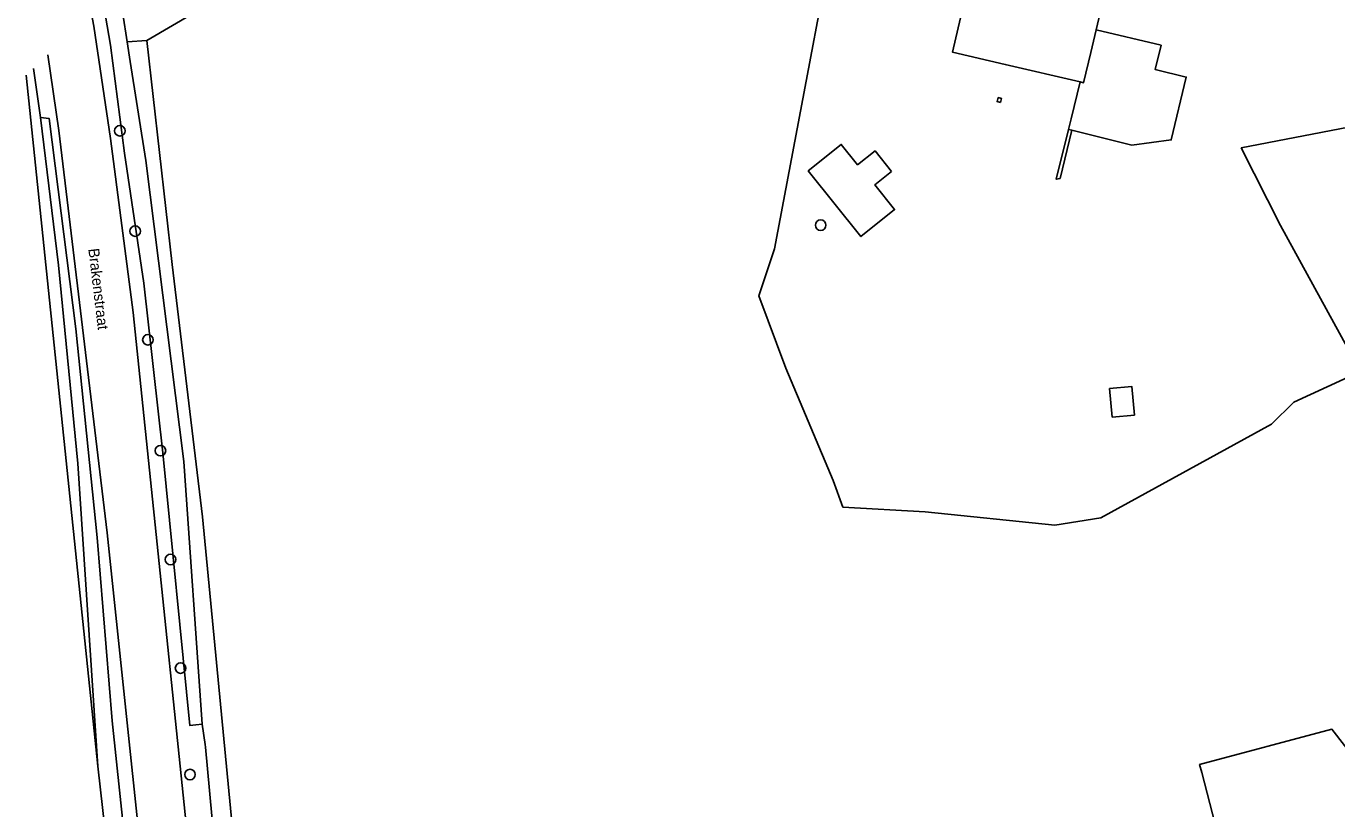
# Model space of a CAD drawing. Extents: x 163863 to 164644, y 379566 to 382155.
# Drawn here: x 164358.4 to 164479.7, y 382019.3 to 382091.7 of the extents above; entities that cross this region are included whole.
import ezdxf

# ---------------------------------------------------------------- set-up
doc = ezdxf.new("R2010")
doc.units = 0
for name, color, linetype in [('IMGEO_Boom', 7, 'Continuous'), ('IMGEO_Grasland_agrarisch', 7, 'Continuous'), ('IMGEO_Grasland_overig', 7, 'Continuous'), ('IMGEO_Hek', 7, 'Continuous'), ('IMGEO_Loofbos', 7, 'Continuous'), ('IMGEO_Muur', 7, 'Continuous'), ('IMGEO_Openbare_ruimte_label', 7, 'Continuous'), ('IMGEO_Pand', 7, 'Continuous'), ('IMGEO_Rijbaan_lokaal_halfverhard', 7, 'Continuous'), ('IMGEO_Waterloop', 7, 'Continuous')]:
    doc.layers.add(name, color=color, linetype=linetype)

msp = doc.modelspace()

# ---------------------------------------------------------------- linework, layer by layer
at = {"layer": 'IMGEO_Boom'}
for centre in [(164367.08, 382082.06), (164368.5, 382072.77), (164431.95, 382073.32), (164369.68, 382062.71), (164370.84, 382052.45), (164371.77, 382042.37), (164372.7, 382032.32), (164373.58, 382022.46)]:
    msp.add_circle(centre, 0.489, dxfattribs=at)
at = {"layer": 'IMGEO_Grasland_agrarisch'}
for points in [[(164489.95, 382084.16), (164470.87, 382080.47), (164474.51, 382073.3), (164481.92, 382059.76), (164475.75, 382056.93), (164473.68, 382054.91), (164457.89, 382046.24), (164453.63, 382045.54), (164441.62, 382046.78), (164434.01, 382047.23), (164433.1, 382049.68), (164428.71, 382060.09), (164426.21, 382066.78), (164427.68, 382071.12), (164435.11, 382110.54)], [(164387.83, 382106.04), (164385.99, 382095.61), (164373.96, 382092.98), (164369.59, 382090.41)]]:
    msp.add_lwpolyline(points, dxfattribs=at)
at = {"layer": 'IMGEO_Grasland_overig'}
for points in [[(164367.77, 382090.28), (164369.59, 382090.41)], [(164369.59, 382090.41), (164371.92, 382069.69), (164374.73, 382046.33), (164377.32, 382019.35), (164380.2, 381990.41), (164381.79, 381978.08)], [(164374.69, 382027.13), (164374.98, 382025.23), (164375, 382024.99), (164377.32, 381999.91), (164378.62, 381987.8), (164379.45, 381980.13), (164379.72, 381978.95)], [(164498.03, 382004.23), (164485.7, 382001.51), (164473.39, 381998.73), (164467.22, 382022.66), (164467.02, 382023.39), (164479.26, 382026.66), (164481.61, 382023.65), (164483.42, 382017.63), (164484.77, 382010.15), (164484.92, 382009.26), (164491.77, 382011.05), (164494.28, 382009.65), (164498.03, 382004.23)]]:
    msp.add_lwpolyline(points, dxfattribs=at)
at = {"layer": 'IMGEO_Hek'}
msp.add_lwpolyline([(164358.42, 382087.21), (164365.06, 382023.24)], dxfattribs=at)
at = {"layer": 'IMGEO_Loofbos'}
for points in [[(164359.08, 382087.82), (164359.75, 382083.3)], [(164365.06, 382023.24), (164358.42, 382087.21)]]:
    msp.add_lwpolyline(points, dxfattribs=at)
at = {"layer": 'IMGEO_Muur'}
msp.add_lwpolyline([(164455.21, 382082.11), (164454.11, 382077.65), (164453.76, 382077.58), (164454.89, 382082.19)], dxfattribs=at)
at = {"layer": 'IMGEO_Pand'}
for points in [[(164455.96, 382086.58), (164449.04, 382088.21), (164444.15, 382089.35), (164445.11, 382093.44), (164445.13, 382093.51), (164441.98, 382094.25), (164443.53, 382100.82), (164443.27, 382100.89), (164441.68, 382101.29), (164442.38, 382104.17)], [(164460.32, 382103.62), (164457.45, 382091.42)], [(164457.45, 382091.42), (164463.45, 382089.97), (164462.91, 382087.72), (164465.79, 382087.03), (164464.39, 382081.22), (164460.74, 382080.74), (164455.21, 382082.11)], [(164457.45, 382091.42), (164456.96, 382089.32), (164456.29, 382086.5), (164455.96, 382086.58)], [(164454.89, 382082.19), (164455.13, 382083.17), (164455.96, 382086.58)], [(164448.58, 382084.68), (164448.28, 382084.76), (164448.38, 382085.13), (164448.68, 382085.05), (164448.58, 382084.68)], [(164454.89, 382082.19), (164455.21, 382082.11)], [(164438.51, 382078.3), (164436.95, 382077.05), (164438.79, 382074.76), (164435.68, 382072.26), (164430.8, 382078.35), (164433.85, 382080.8), (164435.36, 382078.91), (164436.98, 382080.2), (164438.51, 382078.3)], [(164461.01, 382055.74), (164458.93, 382055.55), (164458.69, 382058.19), (164460.76, 382058.38), (164461.01, 382055.74)]]:
    msp.add_lwpolyline(points, dxfattribs=at)
at = {"layer": 'IMGEO_Rijbaan_lokaal_halfverhard'}
for points in [[(164394.68, 381881.88), (164388.1, 381917.44), (164387.74, 381919.59), (164379.47, 381969.66), (164377.03, 381983.08), (164376.33, 381987.84), (164375.07, 382000), (164368.33, 382065.24), (164366.23, 382081.36), (164364.66, 382091.74), (164362.19, 382105.09)], [(164360.43, 382089.08), (164361.43, 382082.09), (164365.91, 382044.84), (164370.62, 382000), (164372.7, 381981.96), (164377.52, 381953.78), (164381.31, 381930.61), (164383.71, 381918.93), (164384.14, 381916.84), (164390.52, 381880.76)]]:
    msp.add_lwpolyline(points, dxfattribs=at)
at = {"layer": 'IMGEO_Waterloop'}
for points in [[(164365.2, 382106.99), (164365.73, 382102.34), (164366.27, 382099.76), (164367.36, 382092.89), (164367.77, 382090.28)], [(164363.36, 382106.67), (164366.21, 382089.98), (164367.5, 382080), (164369.31, 382067.96), (164371.07, 382052.25), (164373.56, 382027.01), (164374.12, 382027.07), (164374.69, 382027.13)], [(164367.77, 382090.28), (164368.05, 382088.47), (164369.5, 382079.3), (164372.99, 382051.45), (164374.69, 382027.13)], [(164365.06, 382023.24), (164363.18, 382051.25), (164361.4, 382069.61), (164359.75, 382083.3)], [(164359.75, 382083.3), (164360.54, 382083.2), (164363.01, 382063.74), (164364.97, 382044.42), (164366.37, 382027.45), (164369.27, 382000), (164371.04, 381984.97), (164371.58, 381977.88), (164371.64, 381973.47), (164370.45, 381973.61)], [(164370.45, 381973.61), (164369.98, 381979.41), (164367.67, 382000), (164365.06, 382023.24)]]:
    msp.add_lwpolyline(points, dxfattribs=at)

# ---------------------------------------------------------------- texts
at = {"layer": 'IMGEO_Openbare_ruimte_label'}
msp.add_text('Brakenstraat', height=1, rotation=276.8337, dxfattribs=at).set_placement((164364.16, 382071.12))

doc.saveas('drawing.dxf')
